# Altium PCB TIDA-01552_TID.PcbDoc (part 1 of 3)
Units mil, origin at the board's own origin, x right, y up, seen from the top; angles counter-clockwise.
Board outline 6250 x 2150 mil, 4 copper layers (Top Layer, Signal Layer 1, Signal Layer 2, Bottom Layer), stack 62.6 mil thick; 251 components, 249 nets, 926 pads, 730 vias.
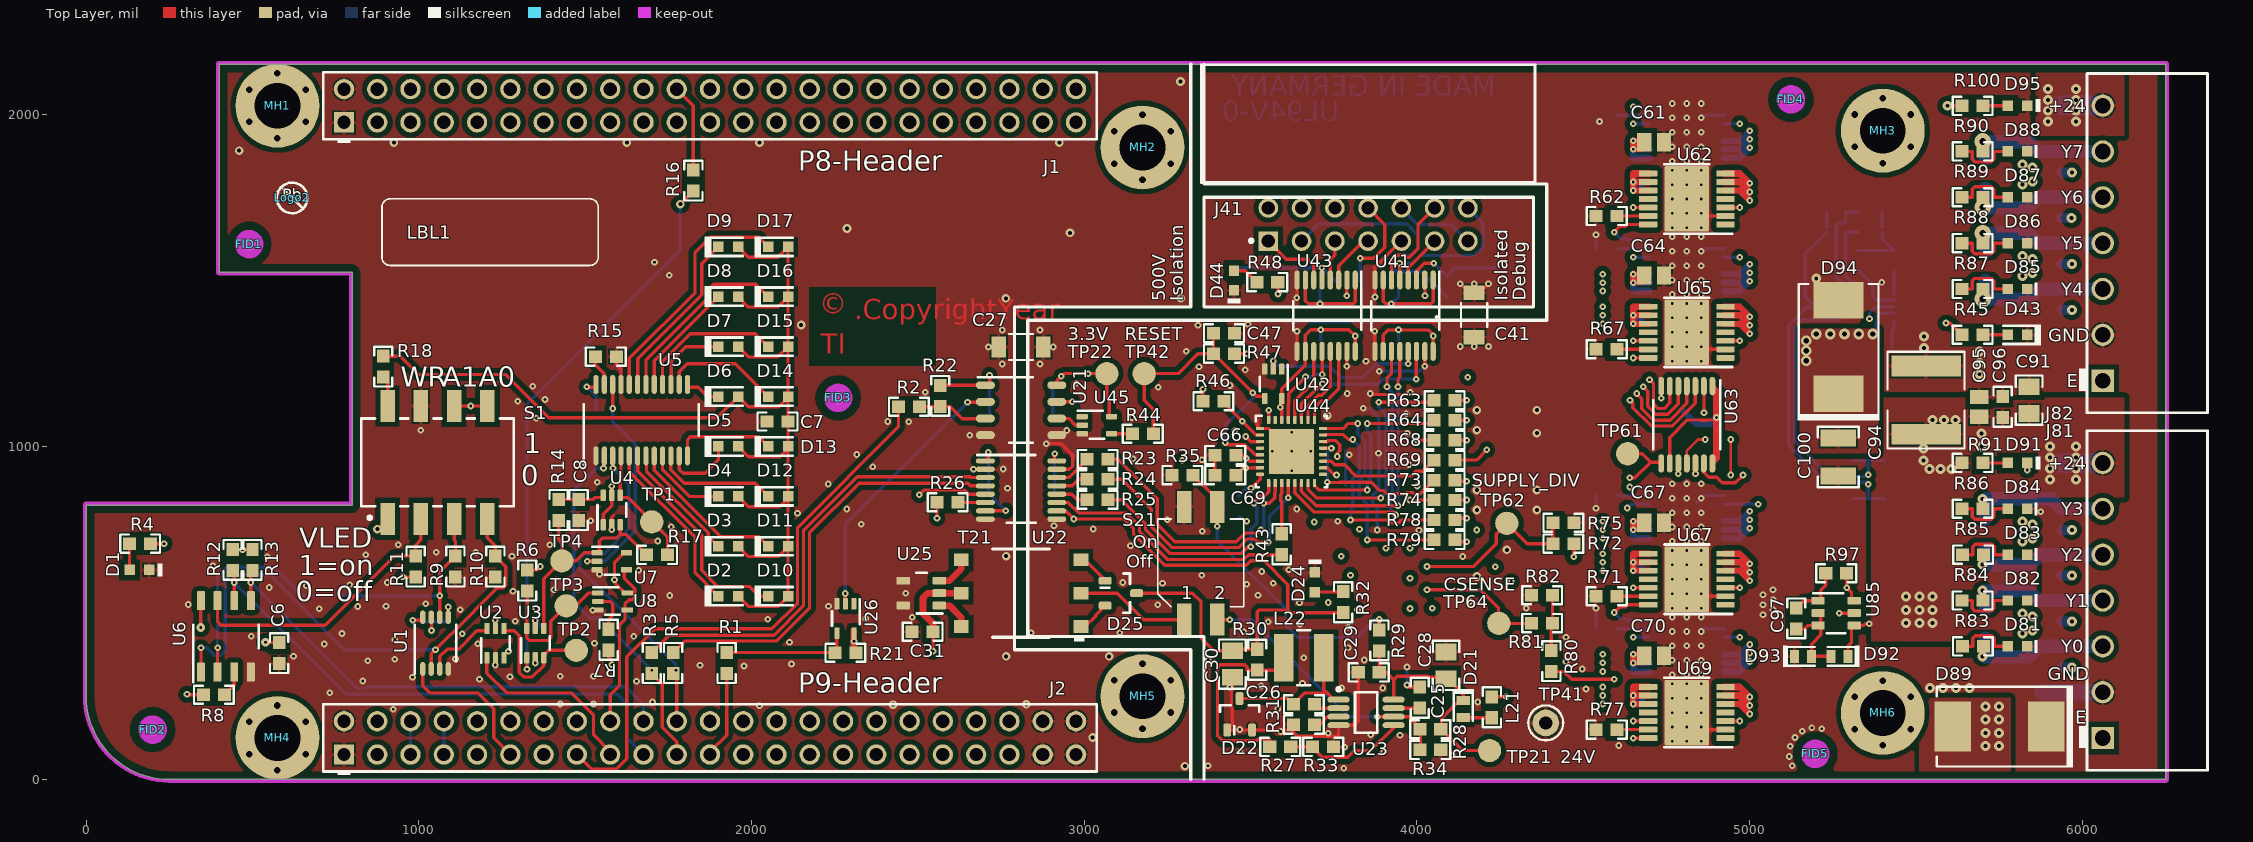
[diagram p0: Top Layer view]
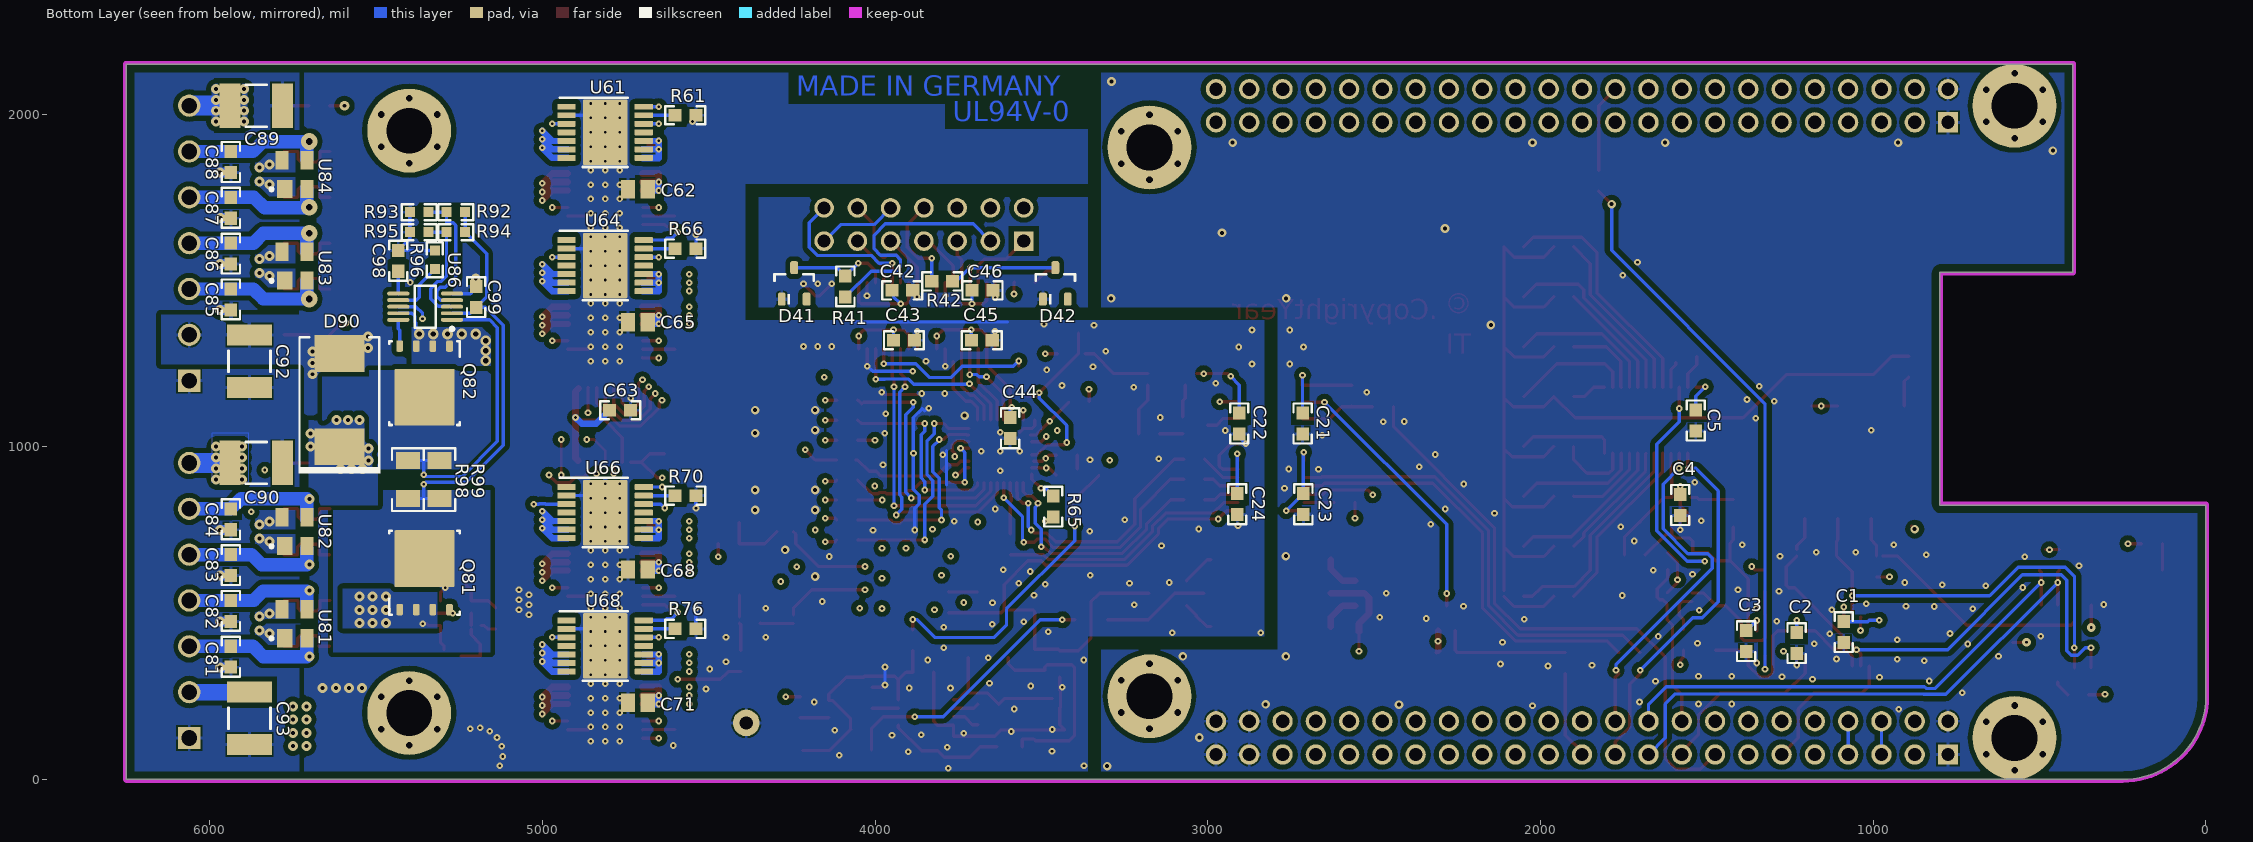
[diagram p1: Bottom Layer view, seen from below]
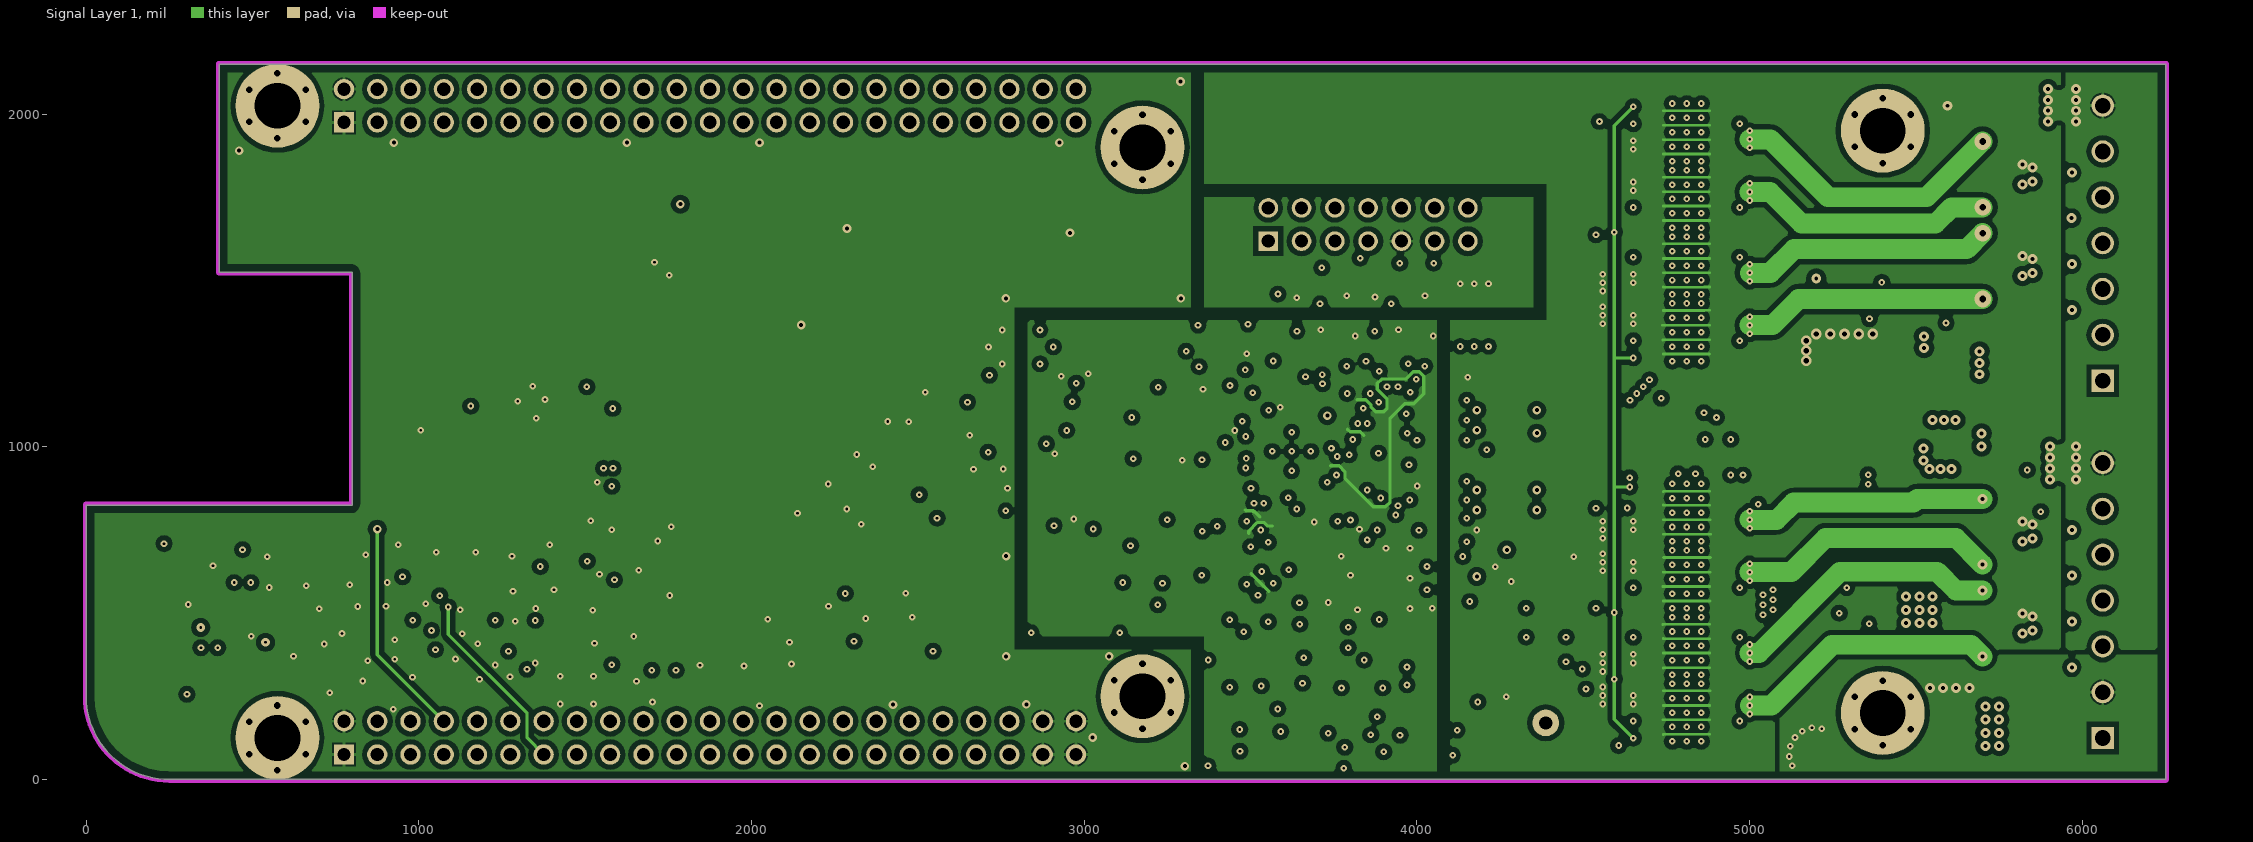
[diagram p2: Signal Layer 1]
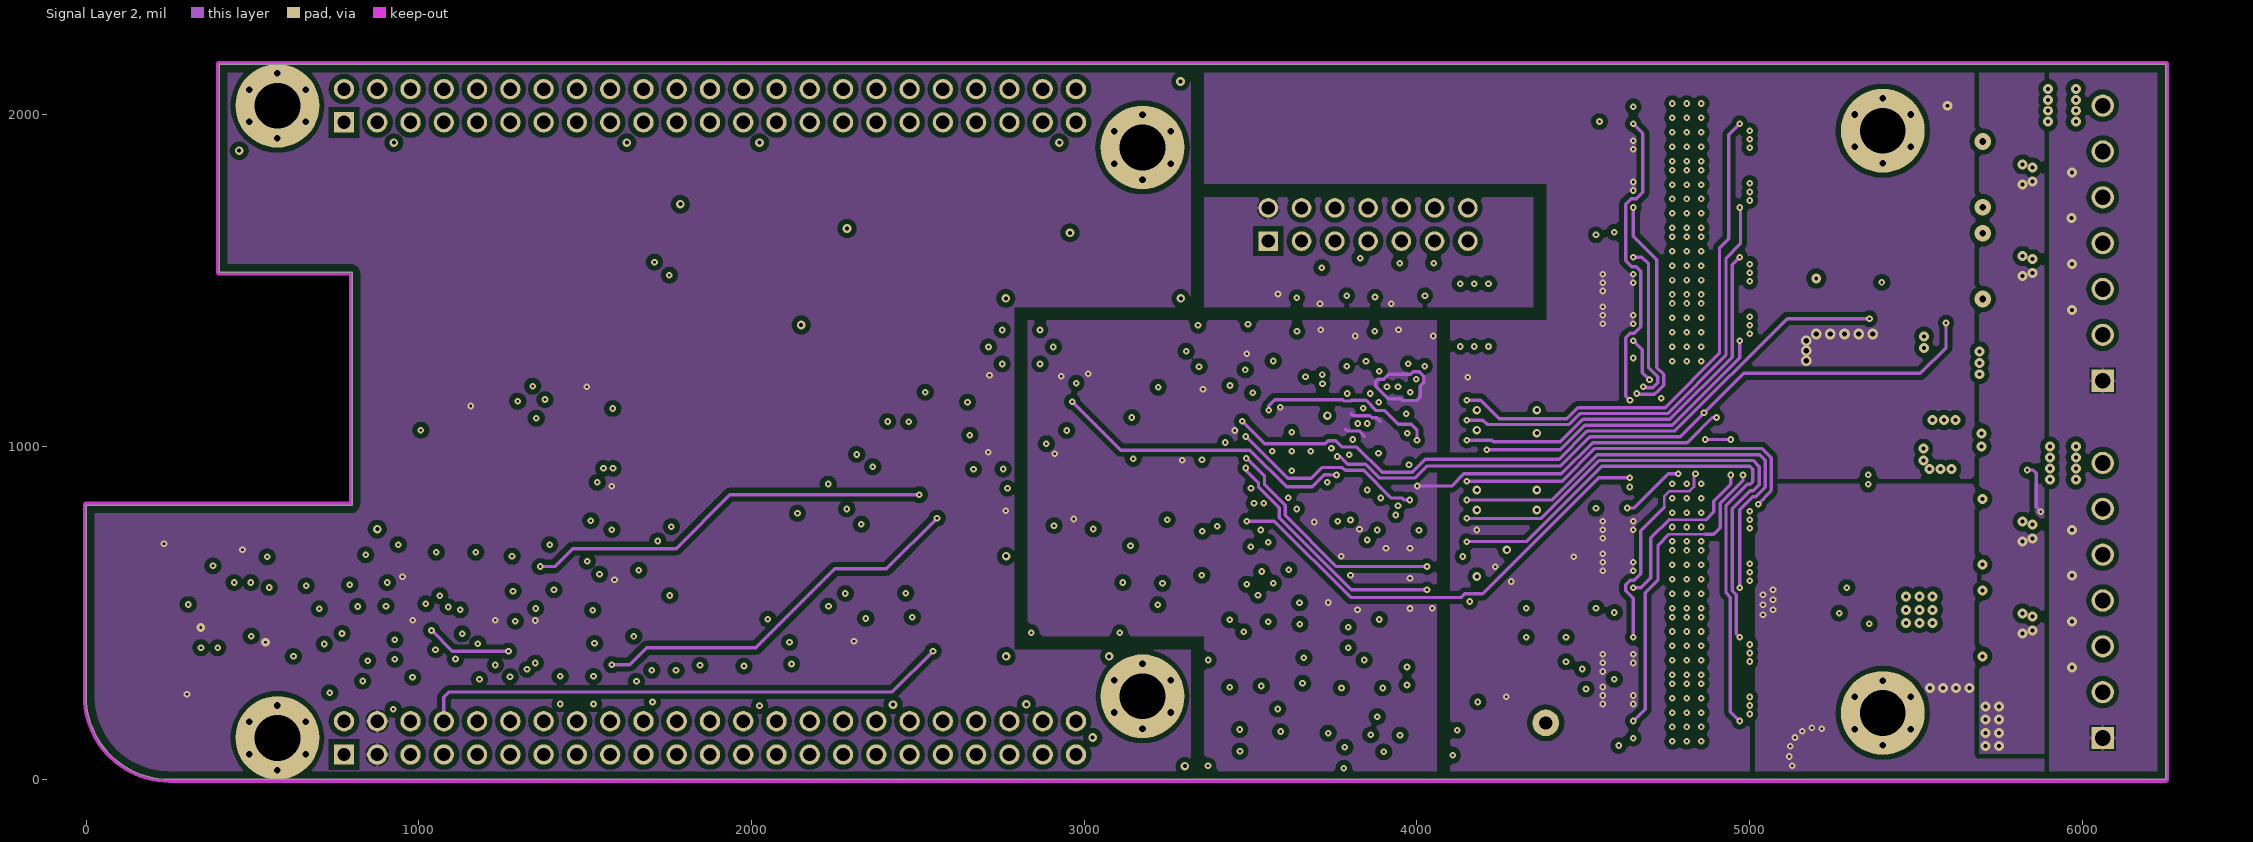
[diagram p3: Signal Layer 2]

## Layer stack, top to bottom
Top Solder: solder mask 0.4, Solder Resist, Dk 3.5
Top Layer: signal copper 1.4
Dielectric1: prepreg 15, FR-4, Dk 4.2
Signal Layer 1: signal copper 1.4
Dielectric 2: core 27, FR-4, Dk 4.2
Signal Layer 2: signal copper 1.4
Dielectric 4: prepreg 15, FR-4, Dk 4.2
Bottom Layer: signal copper 1.4
Bottom Solder: solder mask 0.4, Solder Resist, Dk 3.5

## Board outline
250,0 cw(c250,250) 0,250 0,825 800,825 800,1525 400,1525 400,2150 6250,2150 6250,0

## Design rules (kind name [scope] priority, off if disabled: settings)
AcuteAngle [All] p1: minimum=3.00000000000000E+0001 checktracksonly=FALSE
AssemblyTestPointUsage [All] p1: valid=2
Clearance Clearance_BoardEdge_MountingHoles [OnCopper and InComponentClass('Mounting Holes') vs IsKeepOut] p1: gap=40 ignorepadtopadclearanceinfootprint=FALSE except(0: Arc-Hole Track-Hole SMDPad-Hole THPad-Hole Via-Hole Fill-Hole Poly-Hole Region-Hole Text-Hole)
Clearance Clearance_BoardEdge_Poly [OnCopper and InPoly vs IsKeepOut] p2: gap=25 ignorepadtopadclearanceinfootprint=FALSE except(0: Arc-Hole Track-Hole SMDPad-Hole THPad-Hole Via-Hole Fill-Hole Poly-Hole Region-Hole Text-Hole)
Clearance Clearance_BoardEdge [OnCopper and Not InComponentClass('Logo') and not InComponentClass('FiducialMark') and not InRegion(1000,500,4000,800) and Not IsKeepout and not name like 'MH*' vs IsKeepOut] p3: gap=24 ignorepadtopadclearanceinfootprint=FALSE except(0: Arc-Hole Track-Hole SMDPad-Hole THPad-Hole Via-Hole Fill-Hole Poly-Hole Region-Hole Text-Hole)
Clearance Clearance_Poly [InPolygon] p4: gap=15 ignorepadtopadclearanceinfootprint=TRUE except(0: Arc-Hole Track-Hole SMDPad-Hole THPad-Hole Via-Hole Fill-Hole Poly-Hole Region-Hole Text-Hole)
Clearance [not name like 'fid*'] p5: gap=7.5 ignorepadtopadclearanceinfootprint=TRUE except(0: Arc-Hole Track-Hole SMDPad-Hole THPad-Hole Via-Hole Fill-Hole Poly-Hole Region-Hole Text-Hole)
ComponentClearance ComponentClearance_Shunt [InComponentClass('Header') vs InComponentClass('Shunt')] p1: gap=0 collisioncheckmode=3 verticalgap=0 showdistances=FALSE
ComponentClearance ComponentClearance_MountingHoles_FiducialMarks [InComponentClass('Mounting Holes') vs InComponentClass('FiducialMark')] p2: gap=50 collisioncheckmode=3 verticalgap=10 showdistances=FALSE
ComponentClearance ComponentClearance_Logo [InComponentClass('Logo')] p3: gap=50 collisioncheckmode=3 verticalgap=10 showdistances=FALSE
ComponentClearance ComponentClearance_ScrewToNut [(HasFootprint('NY PMS 440 0025 PH')) vs (HasFootprint('Keystone_1902C'))] p4: gap=5 collisioncheckmode=3 verticalgap=10 showdistances=FALSE
ComponentClearance ComponentClearance_MountingHoles [name like 'MH*'] p5: gap=0 collisioncheckmode=3 verticalgap=100000 showdistances=FALSE
ComponentClearance ComponentClearance_SmallPassives [HasFootprint('0201*') or HasFootprint('0402*') or HasFootprint('0508') or HasFootprint('0603*') or HasFootprint('0612') or HasFootprint('0805*') or HasFootprint('0815*') or HasFootprint('0830*') or HasFootprint('1206*') or HasFootprint('1210*') or HasFootprint('1808*') or HasFootprint('1812*') or HasFootprint('1825*') or HasFootprint('2010*') or HasFootprint('2220*') or HasFootprint('2225*') or HasFootprint('2512*') or HasFootprint('2728*') or HasFootprint('3518*') vs HasFootprint('0201*') or HasFootprint('0402*') or HasFootprint('0508') or HasFootprint('0603*') or HasFootprint('0612') or HasFootprint('0805*') or HasFootprint('0815*') or HasFootprint('0830*') or HasFootprint('1206*') or HasFootprint('1210*') or HasFootprint('1808*') or HasFootprint('1812*') or HasFootprint('1825*') or HasFootprint('2010*') or HasFootprint('2220*') or HasFootprint('2225*') or HasFootprint('2512*') or HasFootprint('2728*') or HasFootprint('3518*')] p6: gap=20 collisioncheckmode=3 verticalgap=10 showdistances=FALSE
ComponentClearance ComponentClearance_THtoSMT [IsThruComponent vs IsSMTComponent] p7: gap=90 collisioncheckmode=3 verticalgap=30 showdistances=FALSE
ComponentClearance ComponentClearance_THtoTH [IsThruComponent and not name like ('J8*') vs IsThruComponent and not name like ('J8*')] p8: gap=118.11 collisioncheckmode=3 verticalgap=30 showdistances=FALSE
ComponentClearance [All] p9: gap=38 collisioncheckmode=3 verticalgap=10 showdistances=FALSE
DiffPairsRouting [All] p1: maxlimit=100 minlimit=10 mostfreqgap=10 toplayer_minwidth=15 toplayer_maxwidth=15 toplayer_prefwidth=15 midlayer1_minwidth=15 midlayer1_maxwidth=15 midlayer1_prefwidth=15 midlayer2_minwidth=15 midlayer2_maxwidth=15 midlayer2_prefwidth=15 bottomlayer_minwidth=15 bottomlayer_maxwidth=15 bottomlayer_prefwidth=15 maxuncoupledlength=1000
FabricationTestPointUsage TestPointUsage [All] p1: valid=2 allowmultiple=FALSE
FabricationTestpoint Testpoint [All] p1: side=3 testpointundercomponent=TRUE minsize=40 maxsize=100 preferedsize=60 minholesize=0 maxholesize=40 preferedholesize=32 testpointgrid=1 allowsidetop=TRUE allowsidebottom=TRUE usegrid=TRUE gridtolerance=0.01
FanoutControl Fanout_LCC [IsLCC] p1: bgadir=Out bgaviamode=Centered fanoutstyle=Auto fanoutdirection=Alternating viagrid=1 // Fanout_LCC (Default Rule)
FanoutControl Fanout_BGA [IsBGA] p2: bgadir=Out bgaviamode=Centered fanoutstyle=Auto fanoutdirection=Alternating viagrid=1 // Fanout_BGA (Default Rule)
FanoutControl Fanout_Default [All] p4: bgadir=Out bgaviamode=Centered fanoutstyle=Auto fanoutdirection=Alternating viagrid=1 // Fanout_Default (Default Rule)
FanoutControl Fanout_Small [(CompPinCount < 5)] p5: bgadir=Out bgaviamode=Centered fanoutstyle=Auto fanoutdirection=OutThenIn viagrid=1 // Fanout_Small (Default Rule)
HoleSize [All] p1: absolutevalues=TRUE maxlimit=251 minlimit=7.6 maxpercent=80.000 minpercent=20.000
MinimumAnnularRing MinimumAnnularRing_InPoly [All] p1: minimumring=3
MinimumAnnularRing MinimumAnnularRing_ThermalPadVias [IsVia and InAnyComponent] p2: minimumring=3
MinimumAnnularRing [All] p3: minimumring=9
MinimumSolderMaskSliver MinimumSolderMaskSliver_Logo [InComponentClass('Logo') vs InComponentClass('Logo')] p1: minsoldermaskwidth=0.7
MinimumSolderMaskSliver [All] p2: minsoldermaskwidth=3.94
PlaneClearance [All] p1: clearance=10
PlaneConnect [All] p1: planeconnectstyle=Direct reliefexpansion=15 reliefentries=4 reliefconductorwidth=10 reliefairgap=5
PolygonConnect Polygon2Via [IsVia] p1: connectstyle=Direct reliefconductorwidth=10 reliefentries=4 polygonreliefangle="90 Angle" airgapwidth=10
PolygonConnect ThermalPolygonVia [IsVia AND (ViaDiameter = '50')] p2: connectstyle=Direct reliefconductorwidth=10 reliefentries=4 polygonreliefangle="90 Angle" airgapwidth=10
PolygonConnect ThermalPolygonPad [(ObjectKind = 'Pad') and ((Name Like 'U*') or (Name Like 'D89*') or (Name Like 'D90*') or (Name Like 'D94*') or (Name Like 'R98*') or (Name Like 'R99*') or (Name Like 'Q*'))] p3: connectstyle=Direct reliefconductorwidth=10 reliefentries=4 polygonreliefangle="90 Angle" airgapwidth=10
PolygonConnect [All] p4: connectstyle=Relief reliefconductorwidth=10 reliefentries=4 polygonreliefangle="90 Angle" airgapwidth=5
RoutingVias ThermalPadVias [IsVia and InAnyComponent] p1: holewidth=7.87 width=20 viastyle="Through Hole" minholewidth=7.87 minwidth=10 maxholewidth=20 maxwidth=40
RoutingVias [All] p2: holewidth=16 width=34 viastyle="Through Hole" minholewidth=7.87 minwidth=20 maxholewidth=40 maxwidth=65
SMDToCorner [All] p1: distance=0
ShortCircuit ShortCircuit_MH_Via [name like 'MH*' vs IsVia] p1: allowed=TRUE
ShortCircuit [All] p2: allowed=FALSE
SilkToBoardRegionClearance [All] p1 off:
SilkToSilkClearance [All] p1: silktosilkclearance=0
SilkToSolderMaskClearance SilkscreenOverComponentPads [IsPad] p1: minsilkscreentomaskgap=0 clearancetoexposedcopper=TRUE
SolderMaskExpansion [All] p1: expansion=1.97
Width [All] p1: maxlimit=100 minlimit=6 preferedwidth=10 checkconnectedcopper=TRUE
13 further rules are at their usual default settings.

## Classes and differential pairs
component class TIDA-01552_pg-3_MCU: C41 C42 C43 C44 C45 C46 C47 D41 D42 D43 D44 J41 R41 R42 R43 R44 R45 R46 R47 R48 R65 TP41 TP42 U41 U42 U43 U44 U45
component class TIDA-01552_pg-5_OP_Connector: C81 C82 C83 C84 C85 C86 C87 C88 C89 C90 C91 C92 C93 C94 C95 C96 C97 C98 C99 C100 D81 D82 D83 D84 D85 D86 D87 D88 D89 D90 D91 D92 D93 D94 D95 J81 J82 Q81 Q82 R83 R84 R85 R86 R87 R88 R89 R90 R91 R92 R93 R94 R95 R96 R97 R98 R99 R100 U81 U82 U83 U84 U85 U86
component class TIDA-01552_pg-4_Driver: C61 C62 C63 C64 C65 C66 C67 C68 C69 C70 C71 R61 R62 R63 R64 R66 R67 R68 R69 R70 R71 R72 R73 R74 R75 R76 R77 R78 R79 R80 R81 R82 TP61 TP62 TP64 U61 U62 U63 U64 U65 U66 U67 U68 U69
component class TIDA-01552_pg-2_PSU-ISO: C21 C22 C23 C24 C25 C26 C27 C28 C29 C30 C31 D21 D22 D24 D25 L21 L22 R21 R22 R23 R24 R25 R26 R27 R28 R29 R30 R31 R32 R33 R34 R35 S21 T21 TP21 TP22 U21 U22 U23 U25 U26
component class TIDA-01552_TID_Hardware: FID1 FID2 FID3 FID4 FID5 LBL1 Logo2 MH1 MH2 MH3 MH4 MH5 MH6 ZZ1 ZZ2 ZZ3 ZZ4
component class FiducialMark: FID1 FID2 FID3 FID4 FID5
component class AssemblyNote: ZZ1 ZZ2 ZZ3 ZZ4
component class Label: LBL1
component class TIDA-01552_pg-1_BB_Connector: C1 C2 C3 C4 C5 C6 C7 C8 D1 D2 D3 D4 D5 D6 D7 D8 D9 D10 D11 D12 D13 D14 D15 D16 D17 J1 J2 R1 R2 R3 R4 R5 R6 R7 R8 R9 R10 R11 R12 R13 R14 R15 R16 R17 R18 S1 TP1 TP2 TP3 TP4 U1 U2 U3 U4 U5 U6 U7 U8

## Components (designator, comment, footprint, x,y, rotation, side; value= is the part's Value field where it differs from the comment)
C1 "GRM188R71C104KA01D" 0603 1088.39,443 r270 bottom value=0.1uF
C2 "GRM188R71C104KA01D" 0603 1230.07,410 r270 bottom value=0.1uF
C3 "GRM188R71C104KA01D" 0603 1382,416 r270 bottom value=0.1uF
C4 "GRM188R71C104KA01D" 0603 1580,825 r270 bottom value=0.1uF
C5 "GRM188R71C104KA01D" 0603 1533,1079 r270 bottom value=0.1uF
C6 "GRM188R71C104KA01D" 0603 580,380 r270 top value=0.1uF
C7 "GRM188R71C104KA01D" 0603 2078,1076 r180 top value=0.1uF
C8 "GRM1885C1H101JA01D" 0603 1480,810 r90 top value=100pF
C21 "GRM188R71C104KA01D" 0603 2715,1070 r270 bottom value=0.1uF
C22 "GRM188R71C104KA01D" 0603 2905,1070 r270 bottom value=0.1uF
C23 "GRM188R71C104KA01D" 0603 2712.49,827.52 r270 bottom value=0.1uF
C24 "GRM188R71C104KA01D" 0603 2911.04,827.52 r270 bottom value=0.1uF
C25 "GCM188R71H104KA57D" 0603 4008,246 r270 top value=0.1uF
C26 "C0603C223K5RACTU" 0603 3660,226 r180 top value=0.022uF
C27 "202R18W102KV4E" 1206_190 2810,1300 r180 top value=1000pF
C28 "C2012X7S2A105K125AB" 0805_HV 4087,343 r90 top value=1uF
C29 "GCM188R71H104KA57D" 0603 3855,322 r180 top value=0.1uF
C30 "GRM21BR71A475KA73L" 0805_HV 3445,347 r270 top value=4.7uF
C31 "GRM188R71C104KA01D" 0603 2514,444 r180 top value=0.1uF
C41 "202R18W102KV4E" 1206_190 4172,1396 r90 top value=1000pF
C42 "GRM188R71C104KA01D" 0603 3918,1470 r180 bottom value=0.1uF
C43 "GRM188R71C104KA01D" 0603 3913,1320 r180 bottom value=0.1uF
C44 "GRM188R71C104KA01D" 0603 3594,1056 r270 bottom value=0.1uF
C45 "GRM188R71C104KA01D" 0603 3679,1320 r180 bottom value=0.1uF
C46 "GRM188R71C104KA01D" 0603 3677,1470 r180 bottom value=0.1uF
C47 "GRM188R71E102KA01D" 0603 3420,1341 r180 top value=1000pF
C61 "C2012X7S2A105K125AB" 0805L 4713,1915.23 r0 top value=1uF
C62 "C2012X7S2A105K125AB" 0805L 4713,1774.15 r0 bottom value=1uF
C63 "GRM188R71C104KA01D" 0603 4766,1110 r180 bottom value=0.1uF
C64 "C2012X7S2A105K125AB" 0805L 4713,1514.56 r0 top value=1uF
C65 "C2012X7S2A105K125AB" 0805L 4713,1374.15 r0 bottom value=1uF
C66 "CGA3E2X7R2A103K080AA" 0603 3424,975 r180 top value=0.01uF
C67 "C2012X7S2A105K125AB" 0805L 4713,772.15 r0 top value=1uF
C68 "C2012X7S2A105K125AB" 0805L 4713,631.15 r0 bottom value=1uF
C69 "GRM188R71E102KA01D" 0603 3424,915 r180 top value=1000pF
C70 "C2012X7S2A105K125AB" 0805L 4713,372.15 r0 top value=1uF
C71 "C2012X7S2A105K125AB" 0805L 4713,230.15 r0 bottom value=1uF
C81 "C1608X7R2A223K080AA" 0603 5936,369 r270 bottom value=0.022uF
C82 "C1608X7R2A223K080AA" 0603 5936,506.67 r270 bottom value=0.022uF
C83 "C1608X7R2A223K080AA" 0603 5936,644.33 r270 bottom value=0.022uF
C84 "C1608X7R2A223K080AA" 0603 5936,782 r270 bottom value=0.022uF
C85 "C1608X7R2A223K080AA" 0603 5936,1443 r270 bottom value=0.022uF
C86 "C1608X7R2A223K080AA" 0603 5936,1580.67 r270 bottom value=0.022uF
C87 "C1608X7R2A223K080AA" 0603 5935.93,1718.33 r270 bottom value=0.022uF
C88 "C1608X7R2A223K080AA" 0603 5936,1856 r270 bottom value=0.022uF
C89 "1812GC472KA1" 1812 5860,2025.39 r180 bottom value=4700pF
C90 "1812GC472KA1" 1812 5860,951.39 r180 bottom value=4700pF
C91 "08051C472KAT2A" 0805_HV 5840,1140 r90 top value=4700pF
C92 "1812GC472KA1" 1812 5880,1257 r270 bottom value=4700pF
C93 "1812GC472KA1" 1812 5880,184 r270 bottom value=4700pF
C94 "C5750X7S2A106M230KB" 2220_250 5530,1140 r90 top value=10uF
C95 "C2012X7S2A105K125AB" 0805L 5690,1120 r90 top value=1uF
C96 "GRM188R72A104KA35D" 0603 5760,1120 r90 top value=0.1uF
C97 "GRM188R72A104KA35D" 0603 5140,484 r270 top value=0.1uF
C98 "GRM188R71E474KA12D" 0603 5433,1559 r90 bottom value=0.47uF
C99 "GRM188R72A104KA35D" 0603 5199,1450 r90 bottom value=0.1uF
C100 "C3225X7S2A475K200AB" 1210_220 5266,969.33 r270 top value=4.7uF
D1 "LTST-C190KGKT" LED_LTST-C190_G 160,630 r0 top value=Green
D2 "LTST-C190KFKT" LED_LTST-C190 1930,551 r180 top value=Orange
D3 "LTST-C190KFKT" LED_LTST-C190 1930,701 r180 top value=Orange
D4 "LTST-C190KFKT" LED_LTST-C190 1930,851 r180 top value=Orange
D5 "LTST-C190KFKT" LED_LTST-C190 1930,1001 r180 top value=Orange
D6 "LTST-C190KFKT" LED_LTST-C190 1930,1151 r180 top value=Orange
D7 "LTST-C190KFKT" LED_LTST-C190 1930,1301 r180 top value=Orange
D8 "LTST-C190KFKT" LED_LTST-C190 1930,1451 r180 top value=Orange
D9 "LTST-C190KFKT" LED_LTST-C190 1930,1601 r180 top value=Orange
D10 "LTST-C190CKT" LED_LTST-C190_Red 2080,551 r180 top value=Red
D11 "LTST-C190CKT" LED_LTST-C190_Red 2080,701 r180 top value=Red
D12 "LTST-C190CKT" LED_LTST-C190_Red 2080,851 r180 top value=Red
D13 "LTST-C190CKT" LED_LTST-C190_Red 2080,1001 r180 top value=Red
D14 "LTST-C190CKT" LED_LTST-C190_Red 2080,1151 r180 top value=Red
D15 "LTST-C190CKT" LED_LTST-C190_Red 2080,1301 r180 top value=Red
D16 "LTST-C190CKT" LED_LTST-C190_Red 2080,1451 r180 top value=Red
D17 "LTST-C190CKT" LED_LTST-C190_Red 2080,1601 r180 top value=Red
D21 "CD0603-S01575" Diode_0603 4139,212 r270 top value=100V
D22 "BAV70-E3-08" SOT-23 3467,196 r90 top value=70V
D24 "LTST-C190KGKT" LED_LTST-C190_G 3693,593 r90 top value=Green
D25 "BAT54C-7-F" SOT-23 3110,560 r0 top value=30V
D41 "MMBZ5225BLT1G" SOT-23 4243,1491 r90 bottom value=3V
D42 "MMBZ5225BLT1G" SOT-23 3458,1491 r90 bottom value=3V
D43 "LTST-C190CKT" LED_LTST-C190_Red 5805,1336.41 r0 top value=Red
D44 "LTST-C190KGKT" LED_LTST-C190_G 3450,1500 r270 top value=Green
D81 "LB Q39G-L2N2-35-1" "LB Q39G_BLUE" 5805,400.2 r0 top value=Blue
D82 "LB Q39G-L2N2-35-1" "LB Q39G_BLUE" 5805,537.99 r0 top value=Blue
D83 "LB Q39G-L2N2-35-1" "LB Q39G_BLUE" 5805,675.8 r0 top value=Blue
D84 "LB Q39G-L2N2-35-1" "LB Q39G_BLUE" 5805,813.58 r0 top value=Blue
D85 "LB Q39G-L2N2-35-1" "LB Q39G_BLUE" 5805,1474.2 r0 top value=Blue
D86 "LB Q39G-L2N2-35-1" "LB Q39G_BLUE" 5805,1611.99 r0 top value=Blue
D87 "LB Q39G-L2N2-35-1" "LB Q39G_BLUE" 5805,1749.8 r0 top value=Blue
D88 "LB Q39G-L2N2-35-1" "LB Q39G_BLUE" 5805,1887.58 r0 top value=Blue
D89 "5.0SMDJ33A" SMC 5751,159 r180 top value=33V
D90 "SMCJ33CA" SMC 5610,1140 r90 bottom value=33V
D91 "LTST-C190KGKT" LED_LTST-C190_G 5805,951.39 r0 top value=Green
D92 "CD0603-S01575" Diode_0603 5270,370 r180 top value=100V
D93 "CD0603-S01575" Diode_0603 5160,370 r0 top value=100V
D94 "5.0SMDJ33A" SMC 5267,1300 r90 top value=33V
D95 "LTST-C190KGKT" LED_LTST-C190_G 5805,2025.39 r0 top value=Green
FID1 "Fiducial" Fiducial10-20 490,1609 r0 top
FID2 "Fiducial" Fiducial10-20 200,150 r0 top
FID3 "Fiducial" Fiducial10-20 2260,1147 r0 top
FID4 "Fiducial" Fiducial10-20 5124,2044 r0 top
FID5 "Fiducial" Fiducial10-20 5197,77 r0 top
J1 "SSHQ-123-D-08-F-LF" Major_BBB_SSHQ-123-D-08 1875,2025 r0 top
J2 "SSHQ-123-D-08-F-LF" Major_BBB_SSHQ-123-D-08 1875,125 r0 top
J41 "SBH11-PBPC-D07-RA-BK" Sullins_SBH11-PBPC-D07-RA-BK 3853,1668 r0 top
J81 "1844265" Phoenix_1844265 6061,538 r90 top
J82 "1844265" Phoenix_1844265 6061,1612 r90 top
L21 "BLM18KG601SN1D" 0603 4225,217 r270 top value="600 ohm"
L22 "SRN4026-680M" SRN4026 3660,366 r180 top value=68uH
LBL1 "Size: 0.65\" x 0.20 \"" Label_650x200 1214,1645 r0 top
Logo2 "Pb-Free Symbol" Pb-Free_Overlay_Small 619,1748 r0 top
MH1 "MTG_Pads" MTGP_4-40_PanHead 575,2025 r0 top
MH2 "MTG_Pads" MTGP_4-40_PanHead 3175,1900 r0 top
MH3 "MTG_Pads" MTGP_4-40_PanHead 5400,1950 r0 top locked
MH4 "MTG_Pads" MTGP_4-40_PanHead 575,125 r0 top
MH5 "MTG_Pads" MTGP_4-40_PanHead 3175,250 r0 top
MH6 "MTG_Pads" MTGP_4-40_PanHead 5400,200 r0 top
Q81 "CSD18532Q5B" DNK0008A 5353.91,621.52 r90 bottom value=60V
Q82 "CSD18532Q5B" DNK0008A 5353.91,1191.52 r270 bottom value=60V
R1 "CRCW06030000Z0EA" 0603 1925,350 r90 top value=0
R2 "CRCW06030000Z0EA" 0603 2473,1120 r0 top value=0
R3 "CRCW060310R0FKEA" 0603 1700,350 r90 top value=10.0
R4 "CRCW0603453RFKEA" 0603 162,709 r0 top value=453
R5 "CRCW060310R0FKEA" 0603 1764,350 r90 top value=10.0
R6 "CRCW060310R0FKEA" 0603 1326,598 r90 top value=10.0
R7 "CRCW060310R0FKEA" 0603 1570,420 r270 top value=10.0
R8 "CRCW06035K62FKEA" 0603 384,255 r180 top value=5.62k
R9 "CRCW06035K62FKEA" 0603 1110,640 r90 top value=5.62k
R10 "CRCW06035K62FKEA" 0603 1230,640 r90 top value=5.62k
R11 "CRCW06035K62FKEA" 0603 990,640 r270 top value=5.62k
R12 "CRCW06035K62FKEA" 0603 440,660 r90 top value=5.62k
R13 "CRCW06035K62FKEA" 0603 500,660 r90 top value=5.62k
R14 "CRCW06035K62FKEA" 0603 1420,810 r270 top value=5.62k
R15 "CRCW060321K0FKEA" 0603 1562,1271 r0 top value=21.0k
R16 "CRCW060310R0FKEA" 0603 1825,1800 r270 top value=10.0
R17 "CRCW06030000Z0EA" 0603 1716,675 r0 top value=0
R18 "CRCW060310R0FKEA" 0603 893,1241 r270 top value=10.0
R21 "CRCW06035K62FKEA" 0603 2282,381 r0 top value=5.62k
R22 "CRCW06035K62FKEA" 0603 2567,1153 r90 top value=5.62k
R23 "CRCW060310R0FKEA" 0603 3040,963 r180 top value=10.0
R24 "CRCW060310R0FKEA" 0603 3040,902 r180 top value=10.0
R25 "CRCW060310R0FKEA" 0603 3040,841 r180 top value=10.0
R26 "CRCW060310R0FKEA" 0603 2589,833 r180 top value=10.0
R27 "CRCW0603649RFKEA" 0603 3589,98 r0 top value=649
R28 "CRCW060366K5FKEA" 0603 4040,151 r0 top value=66.5k
R29 "CRCW060366K5FKEA" 0603 3887,418 r270 top value=66.5k
R30 "CRCW06031R00FKEA" 0603 3520,360 r90 top value=1.00
R31 "CRCW060386K6FKEA" 0603 3660,165 r0 top value=86.6k
R32 "CRCW0603453RFKEA" 0603 3778,533 r90 top value=453
R33 "CRCW06032K00FKEA" 0603 3718,98 r180 top value=2.00k
R34 "CRCW06031M00FKEA" 0603 4040,89 r180 top value=1.00Meg
R35 "CRCW06030000Z0EA" 0603 3295,915 r0 top value=0
R41 "CRCW0603499RFKEA" 0603 4089,1482 r90 bottom value=499
R42 "CRCW0603499RFKEA" 0603 3798,1497 r180 bottom value=499
R43 "CRCW060333R2FKEA" 0603 3593,707 r90 top value=33.2
R44 "CRCW06030000Z0EA" 0603 3176,1039 r0 top value=0
R45 "CRCW0603499RFKEA" 0603 5670,1336.44 r180 top value=499
R46 "CRCW060347K5FKEA" 0603 3388,1137 r0 top value=47.5k
R47 "CRCW060347K5FKEA" 0603 3420,1280 r180 top value=47.5k
R48 "CRCW0603499RFKEA" 0603 3550,1495 r0 top value=499
R61 "CRCW0603806RFKEA" 0603 4570,1996.3 r180 bottom value=806
R62 "CRCW0603806RFKEA" 0603 4570,1693.67 r180 top value=806
R63 "CRCW06031K00FKEA" 0603 4083,1140 r0 top value=1.00k
R64 "CRCW06031K00FKEA" 0603 4083,1080 r0 top value=1.00k
R65 "CRCW060333R2FKEA" 0603 3464.04,820.25 r90 bottom value=33.2
R66 "CRCW0603806RFKEA" 0603 4570,1595.63 r180 bottom value=806
R67 "CRCW0603806RFKEA" 0603 4570,1293 r180 top value=806
R68 "CRCW06031K00FKEA" 0603 4083,1020 r0 top value=1.00k
R69 "CRCW06031K00FKEA" 0603 4083,960 r0 top value=1.00k
R70 "CRCW0603806RFKEA" 0603 4570,853.3 r180 bottom value=806
R71 "CRCW0603806RFKEA" 0603 4570,550.67 r180 top value=806
R72 "CRCW0603316KFKEA" 0603 4440,709 r0 top value=316k
R73 "CRCW06031K00FKEA" 0603 4083,900 r0 top value=1.00k
R74 "CRCW06031K00FKEA" 0603 4083,840 r0 top value=1.00k
R75 "CRCW060316K5FKEA" 0603 4440,772 r180 top value=16.5k
R76 "CRCW0603806RFKEA" 0603 4570,452.63 r180 bottom value=806
R77 "CRCW0603806RFKEA" 0603 4570,150 r180 top value=806
R78 "CRCW06031K00FKEA" 0603 4083,780 r0 top value=1.00k
R79 "CRCW06031K00FKEA" 0603 4083,720 r0 top value=1.00k
R80 "CRCW0603249RFKEA" 0603 4404,356 r270 top value=249
R81 "CRCW06031K00FKEA" 0603 4376,470 r0 top value=1.00k
R82 "CRCW0603249RFKEA" 0603 4376,554 r0 top value=249
R83 "CRCW060310K0FKEA" 0603 5671,400 r0 top value=10.0k
R84 "CRCW060310K0FKEA" 0603 5670,537.97 r0 top value=10.0k
R85 "CRCW060310K0FKEA" 0603 5671.47,675.76 r0 top value=10.0k
R86 "CRCW060310K0FKEA" 0603 5670,813.56 r0 top value=10.0k
R87 "CRCW060310K0FKEA" 0603 5670,1474.24 r0 top value=10.0k
R88 "CRCW060310K0FKEA" 0603 5670,1612.03 r0 top value=10.0k
R89 "CRCW060310K0FKEA" 0603 5670,1749.83 r0 top value=10.0k
R90 "CRCW060310K0FKEA" 0603 5670,1887.62 r0 top value=10.0k
R91 "CRCW060310K0FKEA" 0603 5670,951.35 r0 top value=10.0k
R92 "CRCW060395K3FKEA" 0603_HV 5260,1705 r180 bottom value=95.3k
R93 "CRCW06038K06FKEA" 0603_HV 5370,1705 r180 bottom value=8.06k
R94 "CRCW060347K5FKEA" 0603_HV 5260,1645 r180 bottom value=47.5k
R95 "CRCW060314K0FKEA" 0603_HV 5370,1645 r180 bottom value=14.0k
R96 "CRCW060357K6FKEA" 0603_HV 5323,1562 r270 bottom value=57.6k
R97 "CRCW0603100RFKEA" 0603 5260,620 r0 top value=100
R98 "WSLP1206R0100FEA" 1206 5403.91,901.52 r90 bottom value=0.01
R99 "WSLP1206R0100FEA" 1206 5308.91,901.52 r90 bottom value=0.01
R100 "CRCW060310K0FKEA" 0603 5670,2024.58 r0 top value=10.0k
S1 "219-4LPST" SW_219-4LPST 1056,953 r90 top
S21 "219-2LPST" SW_219-2LPST 3350,650 r90 top
T21 "760390014" Wurth_760390013 2810,560 r180 top value=475uH
TP1 "Pogo Pad" PogoPad 1700,774 r0 top
TP2 "Pogo Pad" PogoPad 1473,388 r0 top
TP3 "Pogo Pad" PogoPad 1443,522 r0 top
TP4 "Pogo Pad" PogoPad 1430,657 r0 top
TP21 "Pogo Pad" PogoPad 4218,87 r90 top
TP22 "Pogo Pad" PogoPad 3068,1220 r90 top
TP41 "5001" Keystone5001 4387,170 r0 top value=Black
TP42 "Pogo Pad" PogoPad 3180,1220 r0 top
TP61 "Pogo Pad" PogoPad 4633,979 r0 top
TP62 "Pogo Pad" PogoPad 4270,770 r90 top
TP64 "Pogo Pad" PogoPad 4246,469 r90 top
U1 "SN74LVC2G86DCTR" DCT0008A_N 1050,410 r90 top
U2 "SN74LVC1G332DCKR" DCK0006A_N 1230,410 r90 top
U3 "SN74LVC1G19DCKR" DCK0006A_N 1350,410 r90 top
U4 "SN74LVC1G58DCKR" DCK0006A_N 1580,810 r90 top
U5 "TLC5928DBQ" DBQ0024A_N 1670,1080 r90 top
U6 "CAT24C256WI-G" SOIC-8 420,430 r90 top
U7 "SN74LVC1G125DCKR" DCK0005A_N 1580,656 r0 top
U8 "SN74LVC1G125DCKR" DCK0005A_N 1582,535 r0 top
U21 "ISO7421DR" D0008A_N 2810,1110 r0 top
U22 "ISO7141CCDBQR" DBQ0016A_N 2810,870 r0 top
U23 "LM5009MM/NOPB" MUA08A_N 3847,201.68 r0 top
U25 "SN6501DBVR" DBV0005A_N 2510,560 r180 top
U26 "SN74LVC1G07DCKR" DCK0005A_N 2282,484 r270 top
U41 "ISO7141CCDBQR" DBQ0016A_N 3961,1394 r270 top
U42 "SN74LVC1G07DCKR" DCK0005A_N 3568,1189 r270 top
U43 "ISO7141FCCDBQR" DBQ0016A_N 3727,1394 r270 top
U44 "MSP430F2112TRHBR" RHB0032E 3623,986 r0 top
U45 "SN74LVC1G07DCKR" DCK0005A_N 3038,1065 r0 top
U61 "TPS27S100BPWPR" PWP0014A_N#1 4811,1945.15 r180 bottom
U62 "TPS27S100BPWPR" PWP0014A_N#2 4811,1744.81 r180 top
U63 "SN74LV164APWR" PW0014A_N 4811,1066.15 r270 top
U64 "TPS27S100BPWPR" PWP0014A_N#1 4811,1544.48 r180 bottom
U65 "TPS27S100BPWPR" PWP0014A_N#2 4811,1344.15 r180 top
U66 "TPS27S100BPWPR" PWP0014A_N#1 4811,802.15 r180 bottom
U67 "TPS27S100BPWPR" PWP0014A_N#2 4811,601.81 r180 top
U68 "TPS27S100BPWPR" PWP0014A_N#1 4811,401.48 r180 bottom
U69 "TPS27S100BPWPR" PWP0014A_N#2 4811,201.15 r180 top
U81 "SR70-02CTG" SOT-143-4 5739,468 r90 bottom value=70V
U82 "SR70-02CTG" SOT-143-4 5739,745 r90 bottom value=70V
U83 "SR70-02CTG" SOT-143-4 5739,1543 r90 bottom value=70V
U84 "SR70-02CTG" SOT-143-4 5739,1818 r90 bottom value=70V
U85 "LM5050MK-1/NOPB" DDC0006A_N 5260,500 r0 top
U86 "LM5069MM-2/NOPB" MUB10A_N 5352,1421 r0 bottom
ZZ1 "This Assembly Note is for PCB labels only" AssemblyNoteLabel 185,3938 r0 top
ZZ2 "This Assembly Note will show in the PcbDoc and associated outputs" AssemblyNote 185,3829.11 r0 top
ZZ3 "This Assembly Note will show in the PcbDoc and associated outputs" AssemblyNote 185,3740.56 r0 top
ZZ4 "This Assembly Note will show in the PcbDoc and associated outputs" AssemblyNote 185,3652 r0 top

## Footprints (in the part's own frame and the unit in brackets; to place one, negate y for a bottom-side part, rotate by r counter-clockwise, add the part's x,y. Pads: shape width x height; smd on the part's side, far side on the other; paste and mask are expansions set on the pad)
0603 [mm] "0603 from SM-752 data"
  rect 1x0.95 smd: 1(-0.8,0) 2(0.8,0)
  silkscreen extent -1.52,-0.69 1.52,0.69, body extent -0.87,-0.47 0.87,0.47, height 0.85
0603_HV [mil] "Ernesto recommended land pattern.  26 mil between pads."
  rect 30x30 smd: 1(-28,0) 2(28,0)
  silkscreen extent -52,-24 52,24, body extent -34,-19 34,19, height 33
0805_HV [mil] "0805 with 30mil clearance between pads"
  rect 50x63 smd: 1(-40,0) 2(40,0)
  silkscreen extent -74,-40 74,40, body extent -43,-29 43,29, height 57
0805L [mm] "0805 from SM-752 data"
  rect 1.1x1.4 smd: 1(-0.75,0) 2(0.75,0)
  body extent -1.1,-0.72 1.1,0.72, height 1.45
1206 [mm] "1206 from SM-752 data"
  rect 1.3x1.85 smd: 1(-1.45,0) 2(1.45,0)
  silkscreen extent -2.4,-1.21 2.4,1.21, body extent -1.7,-0.9 1.7,0.9, height 1.35
1206_190 [mm] "1206_190"
  rect 1.1x1.6 smd: 1(-1.7,0) 2(1.7,0)
  silkscreen extent -0.9,-1 0.9,1, body extent -1.75,-0.95 1.75,0.95, height 1.9
1210_220 [mm] "1210"
  rect 1.3x2.7 smd: 1(-1.45,0) 2(1.45,0)
  silkscreen extent -2.32,-1.57 2.32,1.57, body extent -1.7,-1.35 1.7,1.35, height 2.2
1812 [mm]
  rect 1.6x3.4 smd: 1(-2,0) 2(2,0)
  silkscreen extent -0.8,-1.6 0.8,1.6, body extent -2.4,-1.7 2.4,1.7, height 1.35
2220_250 [mm] "2220"
  rect 1.6x5.3 smd: 1(-2.6,0) 2(2.6,0)
  silkscreen extent -3.69,-2.94 3.69,2.94, body extent -2.95,-2.62 2.95,2.62, height 2.5
AssemblyNote [mil] "Assembly Note"
AssemblyNoteLabel [mil] "Assembly Note for PCB Labels"
D0008A_N [mm] "SOIC, 8-Leads, Body 4.9x3.9mm, Pitch 1.27mm, IPC Medium Density"
  oval 1.45x0.6 smd: 1(-2.725,1.905) 2(-2.725,0.635) 3(-2.725,-0.635) 4(-2.725,-1.905) 5(2.725,-1.905) 6(2.725,-0.635) 7(2.725,0.635) 8(2.725,1.905)
  silkscreen extent -3.3,-2.5 0.9,2.5, body extent -3,-2.45 3,2.45, height 1.63
DBQ0016A_N [mm] "SOP, 16-Leads, Body 4.9x3.9mm, Pitch 0.635mm, IPC Medium Density"
  oval 1.45x0.4 smd: 1(-2.725,2.222) 2(-2.725,1.587) 3(-2.725,0.953) 4(-2.725,0.318) 5(-2.725,-0.318) 6(-2.725,-0.953) 7(-2.725,-1.587) 8(-2.725,-2.222) 9(2.725,-2.222) 10(2.725,-1.587) 11(2.725,-0.953) 12(2.725,-0.318) 13(2.725,0.318) 14(2.725,0.953) 15(2.725,1.587) 16(2.725,2.222)
  silkscreen extent -3.35,-2.5 1.1,2.68, body extent -3.01,-2.45 3.01,2.45, height 1.63
DBQ0024A_N [mm] "SOP, 24-Leads, Body 8.7x3.9mm, Pitch 0.635mm, IPC Medium Density"
  oval 1.45x0.4 smd: 1(-2.725,3.492) 2(-2.725,2.857) 3(-2.725,2.222) 4(-2.725,1.587) 5(-2.725,0.952) 6(-2.725,0.317) 7(-2.725,-0.318) 8(-2.725,-0.953) 9(-2.725,-1.588) 10(-2.725,-2.222) 11(-2.725,-2.857) 12(-2.725,-3.492) 13(2.725,-3.492) 14(2.725,-2.857) 15(2.725,-2.222) 16(2.725,-1.587) 17(2.725,-0.952) 18(2.725,-0.317) 19(2.725,0.318) 20(2.725,0.953) 21(2.725,1.588) 22(2.725,2.222) 23(2.725,2.857) 24(2.725,3.492)
  silkscreen extent -3.4,-4.35 1.2,4.43, body extent -3.01,-4.32 3.01,4.33, height 1.75
DBV0005A_N [mm] "SOT23, 5-Leads, Body 2.9x1.6mm, Pitch 0.95mm, Lead Span 2.8mm, IPC Medium Density"
  rrect17% 1x0.6 smd: 1(-1.375,0.95) 2(-1.375,0) 3(-1.375,-0.95) 4(1.375,-0.95) 5(1.375,0.95)
  silkscreen extent -1.63,-1.55 0.38,1.55, body extent -1.42,-1.46 1.42,1.46, height 1.09
DCK0005A_N [mm] "SOT353, 5-Leads, Body 2x1.3mm, Pitch 0.65mm, Lead Span 2.1mm, IPC Medium Density"
  rrect25% 0.85x0.4 smd: 1(-1.125,0.65) 2(-1.125,0) 3(-1.125,-0.65) 4(1.125,-0.65) 5(1.125,0.65)
  silkscreen extent -1.48,-1.02 0.55,1.1, body extent -1.14,-1 1.14,1, height 0.95
DCK0006A_N [mm] "SOT23, 6-Leads, Body 2x1.3mm, Pitch 0.65mm, Lead Span 2.1mm, IPC Medium Density"
  rrect25% 0.85x0.4 smd: 1(-1.125,0.65) 2(-1.125,0) 3(-1.125,-0.65) 4(1.125,-0.65) 5(1.125,0) 6(1.125,0.65)
  silkscreen extent -1.5,-1.09 0.51,1.09, body extent -1.14,-1 1.14,1, height 0.95
DCT0008A_N [mm] "TSOP, 8-Leads, Body 3x2.8mm, Pitch 0.65mm, IPC Medium Density"
  oval 1.05x0.4 smd: 1(-1.975,0.975) 2(-1.975,0.325) 3(-1.975,-0.325) 4(-1.975,-0.975) 5(1.975,-0.975) 6(1.975,-0.325) 7(1.975,0.325) 8(1.975,0.975)
  silkscreen extent -2.32,-1.57 1.4,1.58, body extent -2.01,-1.47 2.01,1.48, height 1.3
DDC0006A_N [mm]
  rrect17% 1x0.6 smd: 1(-1.375,0.95) 2(-1.375,0) 3(-1.375,-0.95) 4(1.375,-0.95) 5(1.375,0) 6(1.375,0.95)
  silkscreen extent -1.75,-1.52 0.7,1.53, body extent -1.43,-1.48 1.43,1.49, height 0.92
Diode_0603 [mm] "Based on Bourns recommended land pattern Rev 10/09"
  rect 0.7x1 smd: 1(-0.65,0) 2(0.65,0)
  silkscreen extent -1.5,-0.8 0.9,0.8, body extent -0.9,-0.5 0.9,0.5, height 0.85
DNK0008A [mm] "SON, 8-Leads, Body 5x6mm"
  rrect39% 0.86x0.51 smd paste-0.05 mask-0.05: 1(-2.82,1.905) 2(-2.82,0.635) 3(-2.82,-0.635) 4(-2.82,-1.905) 5(2.82,-1.905) 6(2.82,-0.635) 7(2.82,0.635) 8(2.82,1.905)
  rrect8% 1.48x1.27 on Bottom Paste: 9(-0.18,-1.47) 9(-0.18,0) 9(-0.18,1.47) 9(1.5,-1.47) 9(1.5,0) 9(1.5,1.47)
  rrect5% 4.34x4.6 smd paste-3 mask-0.05: 9(1.08,0)
  silkscreen extent -3.2,-2.7 3.2,2.7, body extent -3.05,-2.55 3.05,2.55, height 1.06
Fiducial10-20 [mm]
  round 1 smd mask+0.5: 1(0,0)
  Top Layer keep-out circle w1.178: c0,0 r0.5
Keystone5001 [mil] "For Keystone 500x miniature loop terminals"
  round 80 hole 40: 1(0,0)
  silkscreen extent -52,-52 52,52, body extent -49,-49 49,49, height 182
Label_650x200 [mil] "Thermal Transfer Label"
  round 1 on Mech13: 0(0,0)
  silkscreen extent -325,-100 325,100, body extent -325,-100 325,100, height 1
"LB Q39G_BLUE" [mm] "OSRAM"
  rect 0.8x0.8 smd: 1(-0.75,0) 2(0.75,0)
  silkscreen extent 1.3,-0.5 1.52,0.5, body extent -0.85,-0.45 0.85,0.45, height 0.4
LED_LTST-C190 [mm] "Lite-On"
  rect 0.8x0.8 smd: 1(-0.75,0) 2(0.75,0)
  silkscreen extent -1.1,-0.8 1.8,0.8, body extent -0.85,-0.45 0.85,0.45, height 0.9
LED_LTST-C190_G [mm] "Lite-On"
  rect 0.8x0.8 smd: 1(-0.75,0) 2(0.75,0)
  silkscreen extent 1.38,-0.5 1.75,0.5, body extent -0.85,-0.45 0.85,0.45, height 0.9
LED_LTST-C190_Red [mm] "Lite-On"
  rect 0.8x0.8 smd: 1(-0.75,0) 2(0.75,0)
  silkscreen extent -1.1,-0.8 1.8,0.8, body extent -0.85,-0.45 0.85,0.45, height 0.9
Major_BBB_SSHQ-123-D-08 [mm] "Female Connector, 2.54mm, 23x2, TH"
  rect 1.55x1.55 hole 1.02: 1(-27.94,-1.27)
  round 1.55 hole 1.02: 2(-27.94,1.27) 3(-25.4,-1.27) 4(-25.4,1.27) 5(-22.86,-1.27) 6(-22.86,1.27) 7(-20.32,-1.27) 8(-20.32,1.27) 9(-17.78,-1.27) 10(-17.78,1.27) 11(-15.24,-1.27) 12(-15.24,1.27) 13(-12.7,-1.27) 14(-12.7,1.27) 15(-10.16,-1.27) 16(-10.16,1.27) 17(-7.62,-1.27) 18(-7.62,1.27) 19(-5.08,-1.27) 20(-5.08,1.27) 21(-2.54,-1.27) 22(-2.54,1.27) 23(0,-1.27) 24(0,1.27) 25(2.54,-1.27) 26(2.54,1.27) 27(5.08,-1.27) 28(5.08,1.27) 29(7.62,-1.27) 30(7.62,1.27) 31(10.16,-1.27) 32(10.16,1.27) 33(12.7,-1.27) 34(12.7,1.27) 35(15.24,-1.27) 36(15.24,1.27) 37(17.78,-1.27) 38(17.78,1.27) 39(20.32,-1.27) 40(20.32,1.27) 41(22.86,-1.27) 42(22.86,1.27) 43(25.4,-1.27) 44(25.4,1.27) 45(27.94,-1.27) 46(27.94,1.27)
  silkscreen extent -29.53,-2.85 29.53,2.57, body extent -29.46,-2.51 29.46,2.51, height 8.51
MTGP_4-40_PanHead [mm] "4-40 Mounting Hole, Plated, for Pan Head"
  round 6.4 hole 3.5: 1(0,0)
MUA08A_N [mm] "TSOP, 8-Leads, Body 3x3mm, Pitch 0.65mm, IPC Medium Density"
  oval 1.7x0.45 smd: 1(-2.1,0.975) 2(-2.1,0.325) 3(-2.1,-0.325) 4(-2.1,-0.975) 5(2.1,-0.975) 6(2.1,-0.325) 7(2.1,0.325) 8(2.1,0.975)
  silkscreen extent -2.22,-1.55 0.85,1.87, body extent -1.6,-1.6 1.6,1.6, height 1.09
MUB10A_N [mm] "TSSOP, 10-Leads, Body 3x3mm, Pitch 0.5mm, IPC Medium Density"
  oval 1.7x0.3 smd: 1(-2.05,1) 2(-2.05,0.5) 3(-2.05,0) 4(-2.05,-0.5) 5(-2.05,-1) 6(2.05,-1) 7(2.05,-0.5) 8(2.05,0) 9(2.05,0.5) 10(2.05,1)
  silkscreen extent -2.17,-1.6 0.8,1.82, body extent -1.6,-1.6 1.6,1.6, height 1.09
Pb-Free_Overlay_Small [mil]
  silkscreen extent -46,-46 46,46
Phoenix_1844265 [mm] "TH, 7-Leads, Body 9.2x25.9, Pitch 3.5mm"
  rect 1.7x1.7 hole 1.2: 1(-10.5,0)
  round 1.7 hole 1.2: 2(-7,0) 3(-3.5,0) 4(0,0) 5(3.5,0) 6(7,0) 7(10.5,0)
  silkscreen extent -12.95,-8 12.95,1.8, body extent -12.95,-8 12.95,1.2, height 7.25
PogoPad [mil] "No Solder Paste"
  round 70 smd paste-35: 1(0,0)
PW0014A_N [mm] "TSOP, 14-Leads, Body 5x4.4mm, Pitch 0.65mm, IPC Medium Density"
  oval 1.4x0.45 smd: 1(-2.95,1.95) 2(-2.95,1.3) 3(-2.95,0.65) 4(-2.95,0) 5(-2.95,-0.65) 6(-2.95,-1.3) 7(-2.95,-1.95) 8(2.95,-1.95) 9(2.95,-1.3) 10(2.95,-0.65) 11(2.95,0) 12(2.95,0.65) 13(2.95,1.3) 14(2.95,1.95)
  silkscreen extent -3.4,-2.55 1.85,2.55, body extent -3.21,-2.5 3.21,2.5, height 1
PWP0014A_N#1 [mm] "TSOP, 14-Leads, Body 5x4.4mm, Pitch 0.65mm, Thermal Pad 3x3.1 mm, IPC Medium Density"
  rrect22% 1.4x0.45 smd: 1(-2.95,1.95) 2(-2.95,1.3) 3(-2.95,0.65) 4(-2.95,0) 5(-2.95,-0.65) 6(-2.95,-1.3) 7(-2.95,-1.95) 8(2.95,-1.95) 9(2.95,-1.3) 10(2.95,-0.65) 11(2.95,0) 12(2.95,0.65) 13(2.95,1.3) 14(2.95,1.95)
  rrect6% 3.4x5 smd paste-2 mask-2: 15(0,0)
  rrect3% 3.155x3.255 on Bottom Paste: 15(0,0)
  rrect3% 3.155x3.255 on Bottom Solder: 15(0,0)
  silkscreen extent -3.47,-2.65 1.7,2.65, body extent -3.21,-2.5 3.21,2.5, height 1
PWP0014A_N#2 [mm] "TSOP, 14-Leads, Body 5x4.4mm, Pitch 0.65mm, Thermal Pad 3x3.1 mm, IPC Medium Density"
  rrect22% 1.4x0.45 smd: 1(-2.95,1.95) 2(-2.95,1.3) 3(-2.95,0.65) 4(-2.95,0) 5(-2.95,-0.65) 6(-2.95,-1.3) 7(-2.95,-1.95) 8(2.95,-1.95) 9(2.95,-1.3) 10(2.95,-0.65) 11(2.95,0) 12(2.95,0.65) 13(2.95,1.3) 14(2.95,1.95)
  rrect6% 3.4x5 smd paste-2 mask-2: 15(0,0)
  rrect3% 3.155x3.255 on Top Paste: 15(0,0)
  rrect3% 3.155x3.255 on Top Solder: 15(0,0)
  silkscreen extent -3.47,-2.65 1.7,2.65, body extent -3.21,-2.5 3.21,2.5, height 1
RHB0032E [mm] "QFN, 32-Leads, Body 5x5mm, Pitch 0.5mm, Thermal Pad 3.45x3.45mm, TI Recommended"
  rrect40% 0.6x0.25 smd: 1(-2.4,1.75) 2(-2.4,1.25) 3(-2.4,0.75) 4(-2.4,0.25) 5(-2.4,-0.25) 6(-2.4,-0.75) 7(-2.4,-1.25) 8(-2.4,-1.75) 17(2.4,-1.75) 18(2.4,-1.25) 19(2.4,-0.75) 20(2.4,-0.25) 21(2.4,0.25) 22(2.4,0.75) 23(2.4,1.25) 24(2.4,1.75)
  rrect40% 0.25x0.6 smd: 9(-1.75,-2.4) 10(-1.25,-2.4) 11(-0.75,-2.4) 12(-0.25,-2.4) 13(0.25,-2.4) 14(0.75,-2.4) 15(1.25,-2.4) 16(1.75,-2.4) 25(1.75,2.4) 26(1.25,2.4) 27(0.75,2.4) 28(0.25,2.4) 29(-0.25,2.4) 30(-0.75,2.4) 31(-1.25,2.4) 32(-1.75,2.4)
  rrect3% 3.45x3.45 smd paste-1.725: 33(0,0)
  rrect7% 1.49x1.49 on Top Paste: ""(-0.845,-0.845) ""(-0.845,0.845) ""(0.845,-0.845) ""(0.845,0.845)
  silkscreen extent -2.72,-2.73 2.72,2.73, body extent -2.57,-2.57 2.58,2.58, height 1.01
SMC [mil] "Molded Diode, 2-Leads, Body 6.9x5.8mm, IPC Medium Density, based on OnSemi component dimensions and land patterns"
  rect 110x150 smd: 1(-140.49,0) 2(140.49,0)
  silkscreen extent -221,-124 189,123, body extent -156,-116 156,116, height 91
SOIC-8 [mm] "duplicate of SO-8.  SOIC, 8-Leads, Body 5.0x4.0mm (max), Pitch 1.27mm, IPC Medium Density"
  rrect17% 1.45x0.6 smd: 1(-2.725,1.905) 2(-2.725,0.635) 3(-2.725,-0.635) 4(-2.725,-1.905) 5(2.725,-1.905) 6(2.725,-0.635) 7(2.725,0.635) 8(2.725,1.905)
  silkscreen extent -3.5,-2.5 0.9,2.5, body extent -3,-2.45 3,2.45, height 1.63
SOT-23 [mm] "SOT23, 3-Leads, Body 2.9x1.3mm, Pitch 0.95mm, Lead Span 2.5mm, IPC Medium Density"
  rrect50% 1x0.6 smd: 1(-1.2,0.95) 2(-1.2,-0.95) 3(1.2,0)
  silkscreen extent -1.62,-1.5 0.7,1.5, body extent -1.16,-1.45 1.21,1.45, height 1
SOT-143-4 [mm] "Littelfuse"
  rect 1.4x1.2 smd: 1(-1.1,0.9)
  rect 1.4x1 smd: 2(-1.1,-0.8) 3(1.1,-0.8) 4(1.1,1.1)
  silkscreen extent -1.22,1.8 -1.02,2.01, body extent -0.7,-1.37 0.7,1.67, height 1.23
SRN4026 [mm] "SMD, 2-Leads, Body 4.2x4.2mm"
  rect 1.5x3.6 smd: 1(-1.525,0) 2(1.525,0)
  silkscreen extent -0.5,-2.1 0.5,2.1, body extent -2.1,-2.1 2.1,2.1, height 2.5
Sullins_SBH11-PBPC-D07-RA-BK [mm] "Header (Shrouded), 2.54 mm, 7x2, R/A, TH"
  rect 1.5x1.5 hole 1: 1(-7.62,-1.27)
  round 1.5 hole 1: 2(-7.62,1.27) 3(-5.08,-1.27) 4(-5.08,1.27) 5(-2.54,-1.27) 6(-2.54,1.27) 7(0,-1.27) 8(0,1.27) 9(2.54,-1.27) 10(2.54,1.27) 11(5.08,-1.27) 12(5.08,1.27) 13(7.62,-1.27) 14(7.62,1.27)
  silkscreen extent -12.74,-1.36 12.74,12.21, body extent -12.74,-1.56 12.74,12.21, height 9.3
SW_219-2LPST [mm] "SW, Tape Seal, 2 POS, SMD"
  rect 2.44x1.12 smd: 1(-4.305,1.27) 2(-4.305,-1.27) 3(4.305,-1.27) 4(4.305,1.27)
  silkscreen extent -3.32,-3.27 3.38,3.27, body extent -4.95,-3.28 4.96,3.27, height 4.25
SW_219-4LPST [mil] "SMD, 8-Leads, Body 11.93x6.95mm, Pitch 2.54mm"
  rect 96x44 smd: 1(-169.5,150) 2(-169.5,50) 3(-169.5,-50) 4(-169.5,-150) 5(169.5,-150) 6(169.5,-50) 7(169.5,50) 8(169.5,150)
  silkscreen extent -171,-229 132,229, body extent -195,-229 195,229, height 169
Wurth_760390013 [mil] "Wurth"
  rect 44x38 smd: 1(-180,100) 2(-180,0) 3(-180,-100) 4(180,-100) 5(180,0) 6(180,100)
  silkscreen extent -190,-132 85,145, body extent -198,-135 198,130, height 166

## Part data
C1 C2 C3 C4 C5 C6 C7 C21 C22 C23 C24 C31 C42 C43 C44 C45 C46 C63: "CAP, CERM, 0.1 µF, 16 V, +/- 10%, X7R, 0603", Cap_Case=0603, Manufacturer=MuRata, Supplier Part Number 1=490-1532-1-ND, TempCo=X7R, Tolerance_%=10, Value1=Unknown, Value2=16V, ValueDisplayed=0.1µF
C8: "CAP, CERM, 100 pF, 50 V, +/- 5%, C0G/NP0, 0603", Cap_Case=0603, Manufacturer=MuRata, Supplier Part Number 1=490-1427-1-ND, TempCo=C0G/NP0, Tolerance_%=5, Value1=Unknown, Value2=50V, ValueDisplayed=100pF
C25 C29: "CAP, CERM, 0.1 µF, 50 V, +/- 10%, X7R, 0603", Cap_Case=0603, Manufacturer=MuRata, Supplier Part Number 1=490-4779-1-ND, TempCo=X7R, Tolerance_%=10, Value1="0.02 ohm", Value2=50V, ValueDisplayed=0.1µF
C26: "CAP, CERM, 0.022 µF, 50 V, +/- 10%, X7R, 0603", Cap_Case=0603, Manufacturer=Kemet, Supplier Part Number 1=399-1280-1-ND, TempCo=X7R, Tolerance_%=10, Value1=Unknown, Value2=50V, ValueDisplayed=0.022µF
C27 C41: "CAP, CERM, 1000 pF, 2000 V, +/- 10%, X7R, 1206_190", Cap_Case=1206, Manufacturer="Johanson Technology", TempCo=X7R, Tolerance_%=10, Value1=Unknown, Value2=2000V, ValueDisplayed=1000pF
C28 C61 C62 C64 C65 C67 C68 C70 C71 C95: "CAP, CERM, 1 µF, 100 V,+/- 10%, X7S, 0805", Cap_Case=0805, Manufacturer=TDK, Supplier Part Number 1=445-5205-1-ND, TempCo=X7S, Tolerance_%=10, Value1="0.008255 ohm", Value2=100V, ValueDisplayed=1µF
C30: "CAP, CERM, 4.7 µF, 10 V, +/- 10%, X7R, 0805", Cap_Case=0805, Manufacturer=MuRata, Supplier Part Number 1=GRM21BR71A475KA73L-ND, TempCo=X7R, Tolerance_%=10, Value1=Unknown, Value2=10V, ValueDisplayed=4.7µF
C47 C69: "CAP, CERM, 1000 pF, 25 V, +/- 10%, X7R, 0603", Cap_Case=0603, Manufacturer=MuRata, Supplier Part Number 1=GRM188R71E102KA01D-ND, TempCo=X7R, Tolerance_%=10, Value1=Unknown, Value2=25V, ValueDisplayed=1000pF
C66: "CAP, CERM, 0.01 µF, 100 V,+/- 10%, X7R, AEC-Q200 Grade 1, 0603", Cap_Case=0603, Manufacturer=TDK, Supplier Part Number 1=445-5812-1-ND, TempCo=X7R, Tolerance_%=10, Value1="0.235428 ohm", Value2=100V, ValueDisplayed=0.01µF
C81 C82 C83 C84 C85 C86 C87 C88: "CAP, CERM, 0.022 µF, 100 V,+/- 10%, X7R, 0603", Cap_Case=0603, Manufacturer=TDK, Supplier Part Number 1=445-2275-1-ND, TempCo=X7R, Tolerance_%=10, Value1="0.037 ohm", Value2=100V, ValueDisplayed=0.022µF
C89 C90 C92 C93: "CAP, CERM, 4700 pF, 2000 V, +/- 10%, X7R, 1812", Cap_Case=1812, Manufacturer=AVX, Supplier Part Number 1=581-1812GC472KA11A, TempCo=X7R, Tolerance_%=10, Value1=Unknown, Value2=2000V, ValueDisplayed=4700pF
C91: "CAP, CERM, 4700 pF, 100 V,+/- 10%, X7R, 0805", Cap_Case=0805, Manufacturer=AVX, Supplier Part Number 1=478-1356-1-ND, TempCo=X7R, Tolerance_%=10, Value1="0.119 ohm", Value2=100V, ValueDisplayed=4700pF
C94: "CAP, CERM, 10 µF, 100 V,+/- 20%, X7S, 2220", Cap_Case=2220, Manufacturer=TDK, Supplier Part Number 1=445-5212-1-ND, TempCo=X7S, Tolerance_%=20, Value1="0.005 ohm", Value2=100V, ValueDisplayed=10µF
C96 C97 C99: "CAP, CERM, 0.1 µF, 100 V, +/- 10%, X7R, 0603", Cap_Case=0603, Manufacturer=MuRata, Supplier Part Number 1=490-3285-1-ND, TempCo=X7R, Tolerance_%=10, Value1=Unknown, Value2=100V, ValueDisplayed=0.1µF
C98: "CAP, CERM, 0.47 µF, 25 V, +/- 10%, X7R, 0603", Cap_Case=0603, Manufacturer=MuRata, Supplier Part Number 1=490-3291-1-ND, TempCo=X7R, Tolerance_%=10, Value1=Unknown, Value2=25V, ValueDisplayed=0.47µF
C100: "CAP, CERM, 4.7 µF, 100 V,+/- 10%, X7S, 1210", Cap_Case=1210, Manufacturer=TDK, Supplier Part Number 1=445-6042-1-ND, TempCo=X7S, Tolerance_%=10, Value1="0.004236 ohm", Value2=100V, ValueDisplayed=4.7µF
D1 D24 D44 D91 D95: "LED, Green, SMD", Color=green, Manufacturer=Lite-On, Supplier Part Number 1=160-1435-1-ND, Value1=W, Value2=2V
D2 D3 D4 D5 D6 D7 D8 D9: "LED, Orange, SMD", Color=orange, Manufacturer=Lite-On, Power_TotalModule=0.075, Supplier Part Number 1=160-1434-1-ND, Value1=0.075W, Value2=2V
D10 D11 D12 D13 D14 D15 D16 D17 D43: "LED, Red, SMD", Color=red, Manufacturer=Lite-On, Power_TotalModule=0.0625, Supplier Part Number 1=160-1181-1-ND, Value1=0.0625W, Value2=2V
D21 D92 D93: "Diode, Switching, 100 V, 0.15 A, 0603 Diode", Manufacturer=Bourns, Supplier Part Number 1=652-CD0603-S01575, Value1=0.15A, Value2=1V
D22: "Diode, Switching, 70 V, 0.25 A, SOT-23", Manufacturer=Vishay-Semiconductor, Supplier Part Number 1=BAV70-E3-08CT-ND, Value1=0.25A, Value2=1.25V
D25: "Diode, Schottky, 30 V, 0.2 A, SOT-23", Manufacturer="Diodes Inc.", Supplier Part Number 1=BAT54C-FDICT-ND, Value1=0.2A, Value2=0.65V
D41 D42: "Diode, Zener, 3 V, 225 mW, SOT-23", Manufacturer="ON Semiconductor", Power_W=0.225, Supplier Part Number 1=MMBZ5225BLT1GOSCT-ND, Value1=0.225W
D81 D82 D83 D84 D85 D86 D87 D88: "LED, Blue, SMD", Color=blue, Manufacturer=OSRAM, Supplier Part Number 1=475-2816-1-ND, Value1=W, Value2=2.85V
D89 D94: "Diode, TVS, Uni, 33 V, 5000 W, SMC", Manufacturer=Littelfuse, Power_W=6.5, Supplier Part Number 1=F4119CT-ND, Value1=6.5W
D90: "Diode, TVS, Bi, 33V, 1500W, SMC", Manufacturer=Bourns, Power_W=1500, Supplier Part Number 1=SMCJ33CABCT-ND, Value1=1500W
FID1 FID2 FID3 FID4 FID5: "Fiducial mark.  There is nothing to buy or mount.", Manufacturer=N/A
J1 J2: "Female Connector, 2.54mm, 23x2, TH", Manufacturer="Major League Electronics"
J41: "Header (Shrouded), 2.54 mm, 7x2, Gold, R/A, TH", Manufacturer="Sullins Connector Solutions", Supplier Part Number 1=S9178-ND
J81 J82: "Header (Shrouded), 3.5 mm, 7x1, R/A, TH", Alternate Manufacturer="Phoenix Contact", Alternate PartNumber="MC 1,5/ 7-G-3,5", Supplier Part Number 1=277-5892-ND
L21: "Ferrite Bead, 600 ohm @ 100 MHz, 1.3 A, 0603", Manufacturer=MuRata, Supplier Part Number 1=490-5258-1-ND, Value1="0.15 ohm", Value2=1.3A
L22: "Inductor, Wirewound, Ferrite, 68 µH, 0.35 A, 0.852 ohm, SMD", Manufacturer=Bourns, Supplier Part Number 1=SRN4026-680MCT-ND, Value1="0.852 ohm", Value2=0.35A, ValueDisplayed=68µH
LBL1: library part THT-14-423-10, "Thermal Transfer Printable Labels, 0.650\" W x 0.200\" H - 10,000 per roll", Manufacturer=Brady, Supplier Part Number 1=2065596
Logo2: library part Pb-Free
MH1 MH2 MH3 MH4 MH5 MH6: library part "Mounting Hole (Imperial) with Pads", "PCB Mounting Hole", Manufacturer=Any, PartNumber=N/A
Q81 Q82: "MOSFET, N-CH, 60 V, 172 A, DNK0008A (VSON-CLIP-8)", Alternate Manufacturer=None, Manufacturer="Texas Instruments", Supplier Part Number 1=296-35628-1-ND, Value1="3.3 ohm", Value2="27 nC"
R1 R2 R17 R35 R44: "RES, 0, 5%, 0.1 W, 0603", Manufacturer=Vishay-Dale, Power_W=0.1, Supplier Part Number 1=541-0.0GCT-ND, TempCo="200 ppm/C", Tolerance_%=5, Value1=5%, Value2=0.1W, Value_Code=0000, ValueDisplayed=0
R3 R5 R6 R7 R16 R18 R23 R24 R25 R26: "RES, 10.0, 1%, 0.1 W, 0603", Manufacturer=Vishay-Dale, Power_W=0.1, Supplier Part Number 1=541-10.0HCT-ND, TempCo="100 ppm/C", Tolerance_%=1, Value1=1%, Value2=0.1W, Value_Code=10R0, ValueDisplayed=10.0
R4 R32: "RES, 453, 1%, 0.1 W, 0603", Manufacturer=Vishay-Dale, Power_W=0.1, Supplier Part Number 1=541-453HCT-ND, TempCo="100 ppm/C", Tolerance_%=1, Value1=1%, Value2=0.1W, Value_Code=453R, ValueDisplayed=453
R8 R9 R10 R11 R12 R13 R14 R21 R22: "RES, 5.62 k, 1%, 0.1 W, 0603", Manufacturer=Vishay-Dale, Power_W=0.1, Supplier Part Number 1=541-5.62KHCT-ND, TempCo="100 ppm/C", Tolerance_%=1, Value1=1%, Value2=0.1W, Value_Code=5k62, ValueDisplayed=5.62k
R15: "RES, 21.0 k, 1%, 0.1 W, 0603", Manufacturer=Vishay-Dale, Power_W=0.1, Supplier Part Number 1=541-21.0KHCT-ND, TempCo="100 ppm/C", Tolerance_%=1, Value1=1%, Value2=0.1W, Value_Code=21k0, ValueDisplayed=21.0k
R27: "RES, 649, 1%, 0.1 W, 0603", Manufacturer=Vishay-Dale, Power_W=0.1, Supplier Part Number 1=541-649HCT-ND, TempCo="100 ppm/C", Tolerance_%=1, Value1=1%, Value2=0.1W, Value_Code=649R, ValueDisplayed=649
R28 R29: "RES, 66.5 k, 1%, 0.1 W, 0603", Manufacturer=Vishay-Dale, Power_W=0.1, Supplier Part Number 1=541-66.5KHCT-ND, TempCo="100 ppm/C", Tolerance_%=1, Value1=1%, Value2=0.1W, Value_Code=66k5, ValueDisplayed=66.5k
R30: "RES, 1.00, 1%, 0.1 W, 0603", Manufacturer=Vishay-Dale, Power_W=0.1, Supplier Part Number 1=71-CRCW06031R00FKEA, TempCo="100 ppm/C", Tolerance_%=1, Value1=1%, Value2=0.1W, Value_Code=1R00, ValueDisplayed=1.00
R31: "RES, 86.6 k, 1%, 0.1 W, 0603", Manufacturer=Vishay-Dale, Power_W=0.1, Supplier Part Number 1=541-86.6KHCT-ND, TempCo="100 ppm/C", Tolerance_%=1, Value1=1%, Value2=0.1W, Value_Code=86k6, ValueDisplayed=86.6k
R33: "RES, 2.00 k, 1%, 0.1 W, 0603", Manufacturer=Vishay-Dale, Power_W=0.1, Supplier Part Number 1=541-2.00KHCT-ND, TempCo="100 ppm/C", Tolerance_%=1, Value1=1%, Value2=0.1W, Value_Code=2k00, ValueDisplayed=2.00k
R34: "RES, 1.00 M, 1%, 0.1 W, 0603", Manufacturer=Vishay-Dale, Power_W=0.1, Supplier Part Number 1=541-1.00MHCT-ND, TempCo="100 ppm/C", Tolerance_%=1, Value1=1%, Value2=0.1W, Value_Code=1M00, ValueDisplayed=1.00M
R41 R42 R45 R48: "RES, 499, 1%, 0.1 W, 0603", Manufacturer=Vishay-Dale, Power_W=0.1, Supplier Part Number 1=541-499HCT-ND, TempCo="100 ppm/C", Tolerance_%=1, Value1=1%, Value2=0.1W, Value_Code=499R, ValueDisplayed=499
R43 R65: "RES, 33.2, 1%, 0.1 W, 0603", Manufacturer=Vishay-Dale, Power_W=0.1, Supplier Part Number 1=541-33.2HCT-ND, TempCo="100 ppm/C", Tolerance_%=1, Value1=1%, Value2=0.1W, Value_Code=33R2, ValueDisplayed=33.2
R46 R47: "RES, 47.5 k, 1%, 0.1 W, 0603", Manufacturer=Vishay-Dale, Power_W=0.1, Supplier Part Number 1=541-47.5KHCT-ND, TempCo="100 ppm/C", Tolerance_%=1, Value1=1%, Value2=0.1W, Value_Code=47k5, ValueDisplayed=47.5k
R61 R62 R66 R67 R70 R71 R76 R77: "RES, 806, 1%, 0.1 W, 0603", Manufacturer=Vishay-Dale, Power_W=0.1, Supplier Part Number 1=541-806HCT-ND, TempCo="100 ppm/C", Tolerance_%=1, Value1=1%, Value2=0.1W, Value_Code=806R, ValueDisplayed=806
R63 R64 R68 R69 R73 R74 R78 R79 R81: "RES, 1.00 k, 1%, 0.1 W, 0603", Manufacturer=Vishay-Dale, Power_W=0.1, Supplier Part Number 1=541-1.00KHCT-ND, TempCo="100 ppm/C", Tolerance_%=1, Value1=1%, Value2=0.1W, Value_Code=1k00, ValueDisplayed=1.00k
R72: "RES, 316 k, 1%, 0.1 W, 0603", Manufacturer=Vishay-Dale, Power_W=0.1, Supplier Part Number 1=541-316KHCT-ND, TempCo="100 ppm/C", Tolerance_%=1, Value1=1%, Value2=0.1W, Value_Code=316k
